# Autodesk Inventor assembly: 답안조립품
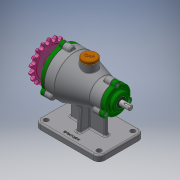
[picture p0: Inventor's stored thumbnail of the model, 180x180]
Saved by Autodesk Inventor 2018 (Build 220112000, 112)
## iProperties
Created: 2020-03
Part Number: 답안조립품
Material: 일반
Document SubType Name: Assembly
Designer: USER
Author: USER
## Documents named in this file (15)
- C:\Users\USER\Desktop\700306V1004\답안조립품.iam
- C:\Users\USER\Desktop\700306V1004\본체.ipt
- C:\Users\USER\Desktop\700306V1004\개스킷 B.ipt
- C:\Users\USER\Desktop\700306V1004\뒤커버.ipt
- C:\Users\USER\Desktop\700306V1004\마개.ipt
- C:\Users\USER\Desktop\700306V1004\베어링 6200.ipt
- C:\Users\USER\Desktop\700306V1004\베어링 6203.ipt
- C:\Users\USER\Desktop\700306V1004\볼트 M5.ipt
- C:\Users\USER\Desktop\700306V1004\스프로킷.ipt
- C:\Users\USER\Desktop\700306V1004\앞커버.ipt
- C:\Users\USER\Desktop\700306V1004\오일 실 10 20 7.ipt
- C:\Users\USER\Desktop\700306V1004\오일 실 17 30 8.ipt
- C:\Users\USER\Desktop\700306V1004\축.ipt
- C:\Users\USER\Desktop\700306V1004\Ű 4x4x14.ipt
- C:\Users\USER\Desktop\700306V1004\개스킷 A.ipt
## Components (3 placed, 3 different names)
1. 개스킷 B:1
2. Ű 4x4x14:1
3. 개스킷 A:1
